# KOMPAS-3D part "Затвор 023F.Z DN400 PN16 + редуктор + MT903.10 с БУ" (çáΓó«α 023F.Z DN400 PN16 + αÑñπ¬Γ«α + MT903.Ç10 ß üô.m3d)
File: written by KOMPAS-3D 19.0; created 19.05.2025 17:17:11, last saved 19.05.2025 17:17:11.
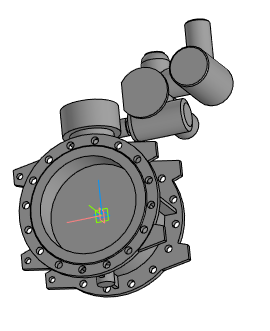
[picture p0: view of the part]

Document properties: Полное имя файла: Затвор 023F.Z DN400 PN16 + редуктор + MT903.10 с БУ.a3d

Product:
- Part/product: Затвор 023F.Z DN400 PN16 + редуктор + MT903.10 с БУ
    Масса: 325.719

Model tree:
1. Операция без истории:1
